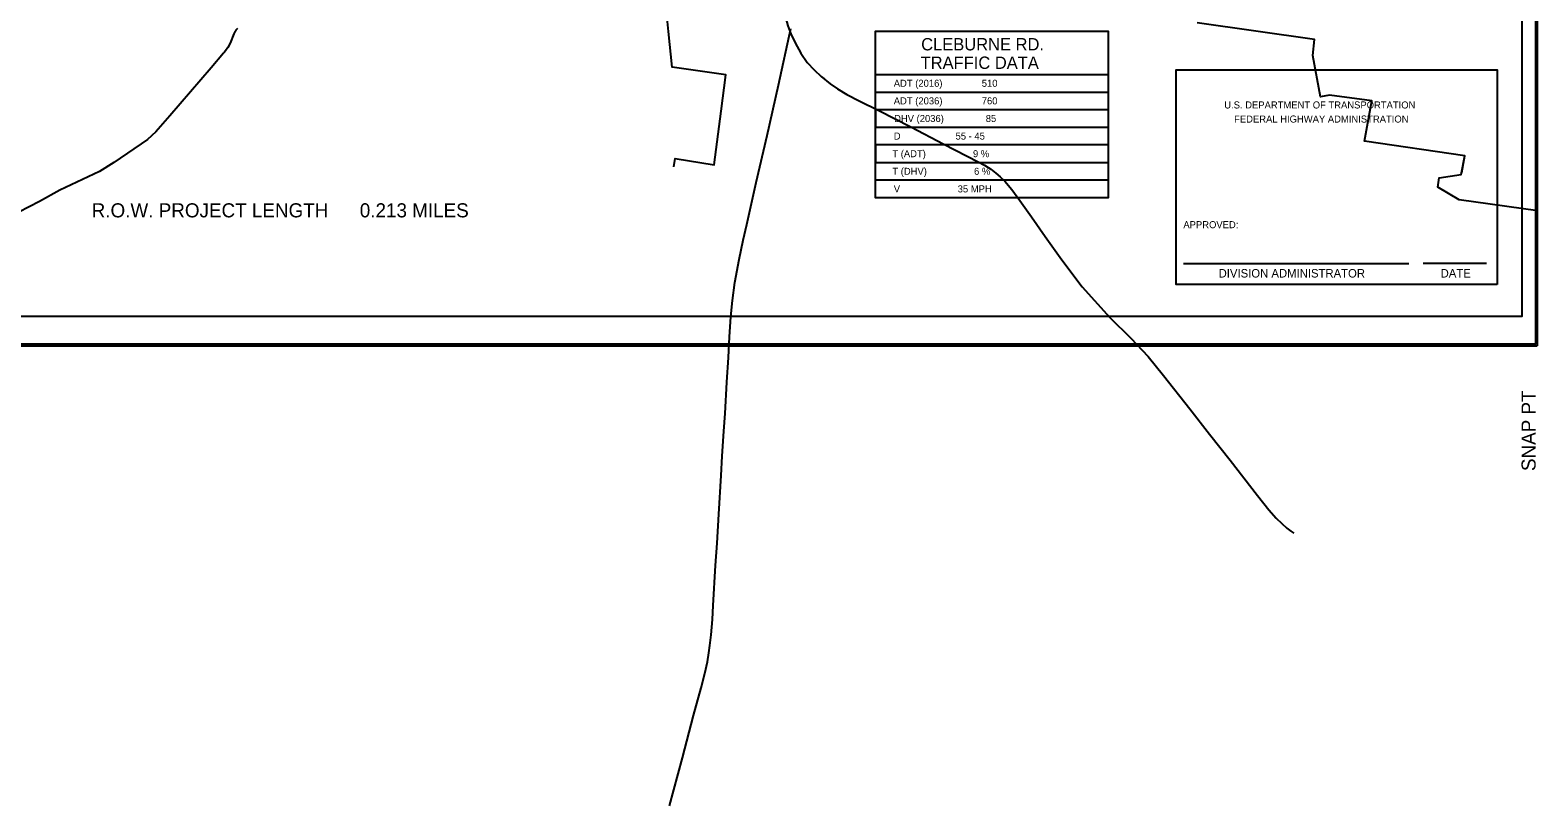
# Model space of a CAD drawing. Extents: x 1577619 to 1828281, y 483481 to 598136.
# Drawn here: x 1672781 to 1715564, y 483481 to 505510 of the extents above; entities that cross this region are included whole.
import ezdxf

# ---------------------------------------------------------------- set-up
doc = ezdxf.new("R2010")
doc.units = 0
for name, color, linetype in [('DESIGN - SCRATCH - User 1', 7, 'Continuous'), ('DESIGN - SHEET - Corner Text', 7, 'Continuous'), ('DESIGN - SHEET - Linework', 7, 'Continuous'), ('DESIGN - SHEET - Plot Shape', 7, 'Continuous'), ('SURVEY - CENTERLINE - Preliminary', 7, 'Continuous'), ('SURVEY - CONTOURS - Index with Text', 7, 'Continuous'), ('SURVEY - CONTROL with Text', 7, 'Continuous'), ('SURVEY - DRAINAGE - Natural Features', 7, 'Continuous'), ('SURVEY - VEGETATION - Features with Text', 7, 'Continuous')]:
    doc.layers.add(name, color=color, linetype=linetype)

msp = doc.modelspace()

# ---------------------------------------------------------------- linework, layer by layer
at = {"layer": 'DESIGN - SCRATCH - User 1'}
msp.add_lwpolyline([(1694095, 510307), (1694098, 509844), (1694116, 509285), (1694125, 508644), (1694130, 507864), (1694136, 507129), (1694136, 506758), (1694154, 506365), (1694184, 506086), (1694224, 505839), (1694284, 505636), (1694369, 505401), (1694486, 505147), (1694651, 504857), (1694834, 504590), (1695026, 504378), (1695230, 504197), (1695301, 504138)], dxfattribs=at)
at = {"layer": 'DESIGN - SHEET - Corner Text'}
for p, q in [((1705505, 498885), (1711905, 498885)), ((1714105, 498885), (1712305, 498885))]:
    msp.add_line(p, q, dxfattribs=at)
at = {"layer": 'DESIGN - SHEET - Linework'}
for p in [(1715541, 540205), (1647461, 496549)]:
    msp.add_line(p, (1715541, 496549), dxfattribs=at)
for points in [[(1652139, 539377), (1715107, 539377), (1715107, 497377), (1652139, 497377), (1652139, 539377)], [(1696769, 504251), (1696769, 505479), (1703369, 505479), (1703369, 500751), (1696769, 500751), (1696769, 504251), (1703369, 504251)], [(1696769, 503751), (1703369, 503751), (1703369, 503251), (1696769, 503251), (1696769, 502751), (1703369, 502751), (1703369, 502251), (1696769, 502251), (1696769, 501751), (1703369, 501751), (1703369, 501251), (1696769, 501251)]]:
    msp.add_lwpolyline(points, dxfattribs=at)
msp.add_lwpolyline([(1714405, 498285), (1705305, 498285), (1705305, 504385), (1714405, 504385)], close=True, dxfattribs=at)
at = {"layer": 'DESIGN - SHEET - Plot Shape'}
for points in [[(1647501, 540165), (1715501, 540165), (1715501, 496589), (1647501, 496589)], [(1648737, 539377), (1715107, 539377), (1715107, 497377), (1648737, 497377)]]:
    msp.add_lwpolyline(points, close=True, dxfattribs=at)
at = {"layer": 'SURVEY - CENTERLINE - Preliminary'}
msp.add_lwpolyline([(1690920, 483481), (1691290, 484847), (1691607, 486049), (1691825, 486835), (1691924, 487236), (1692000, 487572), (1692044, 487824), (1692071, 488032), (1692110, 488336), (1692147, 488771), (1692166, 489167), (1692228, 490307), (1692274, 490939), (1692321, 491768), (1692387, 492864), (1692421, 493410), (1692463, 494125), (1692499, 494626), (1692549, 495515), (1692593, 496218), (1692629, 496796), (1692666, 497371), (1692711, 497833), (1692781, 498346), (1692898, 499001), (1693016, 499541), (1693120, 499989), (1693387, 501184), (1693690, 502519), (1694013, 503946), (1694369, 505553)], dxfattribs=at)
msp.add_lwpolyline([(1690920, 483481), (1691290, 484847), (1691607, 486049), (1691825, 486835), (1691924, 487236), (1692000, 487572), (1692044, 487824), (1692071, 488032), (1692110, 488336), (1692147, 488771), (1692166, 489167), (1692228, 490307), (1692274, 490939), (1692321, 491768), (1692387, 492864), (1692421, 493410), (1692463, 494125), (1692499, 494626), (1692549, 495515), (1692593, 496218), (1692629, 496796), (1692666, 497371), (1692711, 497833), (1692781, 498346), (1692898, 499001), (1693016, 499541), (1693120, 499989), (1693387, 501184), (1693690, 502519), (1694013, 503946), (1694369, 505553)], dxfattribs=at)
at = {"layer": 'SURVEY - CONTOURS - Index with Text'}
msp.add_lwpolyline([(1694284, 505636), (1694369, 505401), (1694486, 505147), (1694651, 504857), (1694834, 504590), (1695026, 504378), (1695230, 504197), (1695484, 503984), (1695692, 503839), (1695959, 503684), (1696309, 503502), (1696868, 503223), (1697768, 502762), (1698707, 502276), (1699686, 501774), (1699859, 501678), (1700042, 501560), (1700183, 501444), (1700310, 501343), (1700441, 501223), (1700638, 500982), (1700867, 500669), (1701192, 500207), (1701588, 499647), (1702053, 498989), (1702635, 498219), (1703422, 497352), (1704014, 496766), (1704502, 496242), (1704944, 495706), (1705692, 494754), (1706247, 494036), (1706833, 493294), (1707608, 492296), (1707934, 491889), (1708141, 491651), (1708296, 491497), (1708441, 491371), (1708556, 491283), (1708641, 491222)], dxfattribs=at)
msp.add_lwpolyline([(1694284, 505636), (1694369, 505401), (1694486, 505147), (1694651, 504857), (1694834, 504590), (1695026, 504378), (1695230, 504197), (1695484, 503984), (1695692, 503839), (1695959, 503684), (1696309, 503502), (1696868, 503223), (1697768, 502762), (1698707, 502276), (1699686, 501774), (1699859, 501678), (1700042, 501560), (1700183, 501444), (1700310, 501343), (1700441, 501223), (1700638, 500982), (1700867, 500669), (1701192, 500207), (1701588, 499647), (1702053, 498989), (1702635, 498219), (1703422, 497352), (1704014, 496766), (1704502, 496242), (1704944, 495706), (1705692, 494754), (1706247, 494036), (1706833, 493294), (1707608, 492296), (1707934, 491889), (1708141, 491651), (1708296, 491497), (1708441, 491371), (1708556, 491283), (1708641, 491222)], dxfattribs=at)
at = {"layer": 'SURVEY - CONTROL with Text'}
msp.add_lwpolyline([(1678661, 505559), (1678620, 505508), (1678609, 505493), (1678600, 505479), (1678567, 505427), (1678557, 505409), (1678456, 505142), (1678390, 505014), (1678325, 504922), (1678286, 504872), (1678268, 504852), (1677913, 504441), (1676744, 503072), (1676351, 502625), (1676115, 502406), (1675159, 501751), (1674745, 501499), (1673627, 500965), (1673042, 500647), (1672162, 500190)], dxfattribs=at)
at = {"layer": 'SURVEY - DRAINAGE - Natural Features'}
for points in [[(1715564, 500383), (1713334, 500694), (1712721, 501052), (1712765, 501315), (1713392, 501406), (1713491, 501942), (1710647, 502360), (1710853, 503505), (1709656, 503660), (1709398, 503617), (1709183, 504794), (1709226, 505246), (1705896, 505721)], [(1713407, 501466), (1713491, 501942), (1710647, 502360), (1710853, 503505), (1709656, 503660), (1709398, 503617), (1709183, 504794), (1709226, 505246), (1705896, 505721)]]:
    msp.add_lwpolyline(points, dxfattribs=at)
at = {"layer": 'SURVEY - VEGETATION - Features with Text'}
msp.add_lwpolyline([(1691042, 501626), (1691086, 501869), (1692192, 501688), (1692388, 503211), (1692519, 504241), (1690996, 504461), (1690892, 505470), (1690753, 506903), (1689217, 507056), (1689391, 508804), (1688881, 508817), (1688912, 509173)], dxfattribs=at)
msp.add_lwpolyline([(1691042, 501626), (1691086, 501869), (1692192, 501688), (1692388, 503211), (1692519, 504241), (1690996, 504461), (1690892, 505470), (1690753, 506903), (1689217, 507056), (1689391, 508804), (1688881, 508817), (1688912, 509173)], dxfattribs=at)

# ---------------------------------------------------------------- texts
at = {"layer": 'DESIGN - SHEET - Corner Text'}
for s, height, p in [('CLEBURNE RD.', 350, (1698065, 504934)), ('TRAFFIC DATA', 350, (1698049, 504409)), ('ADT (2016)               510', 200, (1697287, 503901)), ('ADT (2036)               760', 200, (1697287, 503401)), ('U.S. DEPARTMENT OF TRANSPORTATION', 200, (1706665, 503285)), ('DHV (2036)                85', 200, (1697296, 502901)), ('FEDERAL HIGHWAY ADMINISTRATION', 200, (1706945, 502885)), ('D                     55 - 45', 200, (1697287, 502401)), ('T (ADT)                  9 %', 200, (1697247, 501901)), ('T (DHV)                  6 %', 200, (1697247, 501401)), ('V                      35 MPH', 200, (1697287, 500901)), ('R.O.W. PROJECT LENGTH      0.213 MILES', 400, (1674527, 500193)), ('APPROVED:', 200, (1705505, 499885)), ('DIVISION ADMINISTRATOR', 240, (1706505, 498485)), ('DATE', 240, (1712805, 498485))]:
    msp.add_text(s, height=height, dxfattribs=at).set_placement(p)
msp.add_text('SNAP PT  ', height=400, rotation=90, dxfattribs=at).set_placement((1715501, 492989))

doc.saveas('drawing.dxf')
